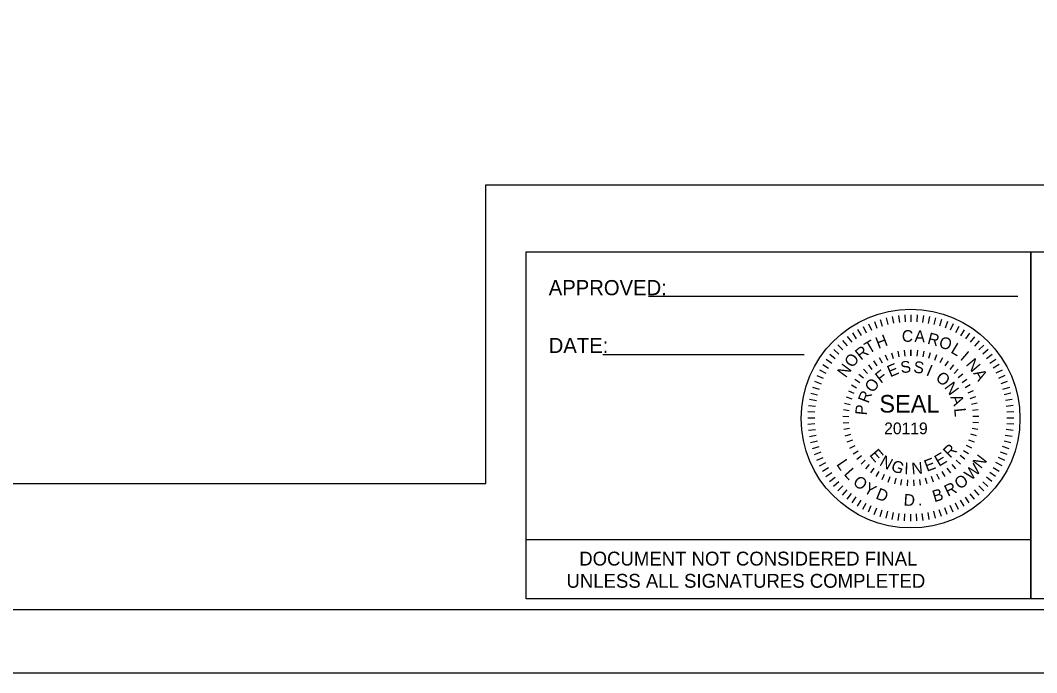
# Model space of a CAD drawing. Extents: x 1613335 to 1618399, y 897277 to 901877.
# Drawn here: x 1616057 to 1617265, y 898577 to 899353 of the extents above; entities that cross this region are included whole.
import ezdxf

# ---------------------------------------------------------------- set-up
doc = ezdxf.new("R2010")
doc.units = 0
for name, color, linetype in [('Default', 7, 'Continuous'), ('DEV BORDER CELL', 7, 'Continuous'), ('Scratch_Level_0', 7, 'Continuous'), ('Sheet Plot Border Outside CELL', 7, 'Continuous'), ('Sheet Sticker Exception Certification CELL', 7, 'Continuous')]:
    doc.layers.add(name, color=color, linetype=linetype)

msp = doc.modelspace()

# ---------------------------------------------------------------- linework, layer by layer
at = {"layer": 'Default'}
for p, q in [((1617072.2, 898994.8), (1617075.1, 898986.9)), ((1617079.2, 898997.2), (1617081.6, 898989.2)), ((1617086.3, 898999.1), (1617088.3, 898991)), ((1617093.5, 899000.7), (1617095, 898992.5)), ((1617100.9, 899001.8), (1617101.9, 898993.5)), ((1617108.2, 899002.5), (1617108.7, 898994.1)), ((1617115.7, 899002.7), (1617115.6, 898994.3)), ((1617123.1, 899002.4), (1617122.6, 898994.1)), ((1617130.4, 899001.8), (1617129.4, 898993.5)), ((1617137.8, 899000.7), (1617136.2, 898992.4)), ((1617145, 898999.1), (1617143, 898991)), ((1617152.1, 898997.1), (1617149.6, 898989.1)), ((1617159.1, 898994.7), (1617156.2, 898986.9)), ((1617046, 898981), (1617050.7, 898974.2)), ((1617052.2, 898985.1), (1617056.5, 898977.9)), ((1617058.7, 898988.7), (1617062.5, 898981.3)), ((1617065.3, 898991.9), (1617068.7, 898984.3)), ((1617166, 898991.8), (1617162.5, 898984.2)), ((1617172.6, 898988.6), (1617168.7, 898981.2)), ((1617179.1, 898984.9), (1617174.7, 898977.8)), ((1617185.3, 898980.9), (1617180.5, 898974)), ((1617034.3, 898971.9), (1617039.8, 898965.7)), ((1617040, 898976.7), (1617045.2, 898970.1)), ((1617191.3, 898976.5), (1617186.1, 898969.9)), ((1617196.9, 898971.8), (1617191.4, 898965.5)), ((1617023.8, 898961.5), (1617030.1, 898955.9)), ((1617028.9, 898966.8), (1617034.8, 898960.9)), ((1617092.5, 898957.5), (1617094.5, 898950.8)), ((1617100.1, 898959.4), (1617101.4, 898952.5)), ((1617107.8, 898960.5), (1617108.5, 898953.6)), ((1617115.6, 898960.9), (1617115.6, 898953.9)), ((1617115.6, 898953.9), (1617115.6, 898960.9)), ((1617123.4, 898960.5), (1617122.7, 898953.6)), ((1617131.1, 898959.4), (1617129.8, 898952.5)), ((1617138.7, 898957.5), (1617136.7, 898950.8)), ((1617202.3, 898966.7), (1617196.4, 898960.8)), ((1617207.4, 898961.3), (1617201.1, 898955.7)), ((1617014.7, 898949.8), (1617021.6, 898945.1)), ((1617019.1, 898955.8), (1617025.7, 898950.6)), ((1617071.3, 898947.7), (1617075.1, 898941.9)), ((1617078, 898951.7), (1617081.3, 898945.5)), ((1617085.1, 898954.9), (1617087.8, 898948.5)), ((1617146.1, 898954.9), (1617143.5, 898948.4)), ((1617153.2, 898951.6), (1617149.9, 898945.4)), ((1617159.9, 898947.6), (1617156.1, 898941.8)), ((1617212.1, 898955.6), (1617205.6, 898950.4)), ((1617216.5, 898949.6), (1617209.6, 898944.9)), ((1617007, 898937.1), (1617014.4, 898933.2)), ((1617010.7, 898943.6), (1617017.8, 898939.3)), ((1617059.1, 898937.9), (1617064, 898932.9)), ((1617065, 898943.1), (1617069.3, 898937.7)), ((1617166.2, 898943), (1617161.8, 898937.6)), ((1617172, 898937.8), (1617167.2, 898932.8)), ((1617220.5, 898943.4), (1617213.4, 898939.1)), ((1617224.2, 898936.9), (1617216.8, 898933.1)), ((1617000.9, 898923.6), (1617008.7, 898920.7)), ((1617003.8, 898930.5), (1617011.4, 898927.1)), ((1617049.1, 898926), (1617054.8, 898922.1)), ((1617053.8, 898932.2), (1617059.1, 898927.7)), ((1617177.4, 898932.1), (1617172, 898927.6)), ((1617182.1, 898925.9), (1617176.4, 898921.9)), ((1617227.4, 898930.3), (1617219.8, 898926.9)), ((1617230.2, 898923.4), (1617222.4, 898920.5)), ((1616996.5, 898909.5), (1617004.6, 898907.5)), ((1616998.5, 898916.7), (1617006.5, 898914.2)), ((1617041.5, 898912.4), (1617047.9, 898909.6)), ((1617044.9, 898919.4), (1617051, 898916)), ((1617186.2, 898919.3), (1617180.1, 898915.9)), ((1617189.7, 898912.3), (1617183.3, 898909.5)), ((1617232.7, 898916.4), (1617224.7, 898914)), ((1617234.6, 898909.3), (1617226.5, 898907.3)), ((1616994.9, 898902.3), (1617003.2, 898900.8)), ((1617036.6, 898897.6), (1617043.4, 898896.1)), ((1617038.7, 898905.1), (1617045.3, 898902.9)), ((1617192.4, 898905), (1617185.8, 898902.8)), ((1617194.5, 898897.4), (1617187.7, 898895.9)), ((1617236.2, 898902), (1617228, 898900.6)), ((1616993.1, 898887.6), (1617001.5, 898887.1)), ((1616993.8, 898894.9), (1617002.1, 898893.9)), ((1617035.3, 898889.9), (1617042.2, 898889)), ((1617195.8, 898889.7), (1617188.9, 898888.9)), ((1617237.3, 898894.7), (1617229, 898893.7)), ((1617237.9, 898887.3), (1617229.6, 898886.9)), ((1616992.9, 898880.2), (1617001.3, 898880.2)), ((1616993.1, 898872.8), (1617001.5, 898873.3)), ((1617034.7, 898882.1), (1617041.7, 898881.9)), ((1617034.9, 898874.3), (1617041.9, 898874.8)), ((1617196.1, 898874.1), (1617189.2, 898874.6)), ((1617196.3, 898881.9), (1617189.4, 898881.8)), ((1617237.9, 898872.5), (1617229.6, 898873)), ((1617238.2, 898879.9), (1617229.8, 898879.9)), ((1616993.8, 898865.4), (1617002.1, 898866.4)), ((1617035.9, 898866.5), (1617042.7, 898867.7)), ((1617037.5, 898858.9), (1617044.3, 898860.7)), ((1617193.5, 898858.7), (1617186.8, 898860.6)), ((1617188.4, 898867.8), (1617195.2, 898866.6)), ((1617237.3, 898865.2), (1617229, 898866.2)), ((1616994.9, 898858.1), (1617003.1, 898859.6)), ((1616996.4, 898850.8), (1617004.6, 898852.8)), ((1617039.9, 898851.5), (1617046.5, 898853.9)), ((1617191.1, 898851.3), (1617184.6, 898853.8)), ((1617234.6, 898850.6), (1617226.5, 898852.6)), ((1617236.1, 898857.8), (1617227.9, 898859.3)), ((1616998.4, 898843.7), (1617006.4, 898846.2)), ((1617000.8, 898836.7), (1617008.7, 898839.6)), ((1617043.1, 898844.3), (1617049.3, 898847.4)), ((1617046.8, 898837.5), (1617052.8, 898841.1)), ((1617184.2, 898837.4), (1617178.2, 898841)), ((1617188, 898844.2), (1617181.7, 898847.3)), ((1617230.2, 898836.5), (1617222.3, 898839.4)), ((1617232.6, 898843.5), (1617224.6, 898846)), ((1617003.7, 898829.8), (1617011.3, 898833.2)), ((1617006.9, 898823.2), (1617014.3, 898827)), ((1617051.3, 898831), (1617056.8, 898835.3)), ((1617056.3, 898825.1), (1617061.4, 898829.8)), ((1617061.9, 898819.6), (1617066.5, 898824.8)), ((1617169.1, 898819.5), (1617164.5, 898824.7)), ((1617174.7, 898825), (1617169.6, 898829.7)), ((1617179.7, 898830.9), (1617174.2, 898835.2)), ((1617224.1, 898823), (1617216.7, 898826.9)), ((1617227.3, 898829.6), (1617219.7, 898833.1)), ((1617010.5, 898816.7), (1617017.7, 898821)), ((1617014.6, 898810.5), (1617021.4, 898815.2)), ((1617068, 898814.7), (1617072.1, 898820.3)), ((1617074.5, 898810.4), (1617078, 898816.4)), ((1617081.4, 898806.8), (1617084.4, 898813.1)), ((1617149.5, 898806.7), (1617146.6, 898813.1)), ((1617156.5, 898810.4), (1617152.9, 898816.4)), ((1617163, 898814.6), (1617158.9, 898820.3)), ((1617216.4, 898810.3), (1617209.5, 898815.1)), ((1617220.4, 898816.5), (1617213.3, 898820.9)), ((1617018.9, 898804.5), (1617025.5, 898809.7)), ((1617023.7, 898798.8), (1617029.9, 898804.4)), ((1617088.7, 898803.8), (1617091, 898810.4)), ((1617097.8, 898808.4), (1617096.1, 898801.6)), ((1617103.8, 898800.1), (1617104.8, 898807)), ((1617111.6, 898799.3), (1617111.9, 898806.3)), ((1617119.4, 898799.3), (1617119, 898806.3)), ((1617127.1, 898800.1), (1617126.1, 898807)), ((1617134.8, 898801.6), (1617133.1, 898808.3)), ((1617142.3, 898803.8), (1617140, 898810.4)), ((1617207.2, 898798.7), (1617201, 898804.2)), ((1617212, 898804.3), (1617205.4, 898809.5)), ((1617028.8, 898793.4), (1617034.7, 898799.3)), ((1617034.1, 898788.3), (1617039.7, 898794.6)), ((1617039.8, 898783.6), (1617045, 898790.2)), ((1617191.1, 898783.5), (1617185.9, 898790)), ((1617196.8, 898788.2), (1617191.2, 898794.5)), ((1617202.2, 898793.3), (1617196.3, 898799.2)), ((1617045.8, 898779.2), (1617050.5, 898786.1)), ((1617052, 898775.2), (1617056.3, 898782.3)), ((1617058.5, 898771.5), (1617062.3, 898778.9)), ((1617065.1, 898768.3), (1617068.5, 898775.9)), ((1617165.8, 898768.2), (1617162.3, 898775.8)), ((1617172.4, 898771.4), (1617168.5, 898778.8)), ((1617178.9, 898775.1), (1617174.6, 898782.2)), ((1617185.1, 898779.1), (1617180.4, 898785.9)), ((1617072, 898765.4), (1617074.9, 898773.3)), ((1617078.9, 898763), (1617081.4, 898771)), ((1617086.1, 898761), (1617088.1, 898769.1)), ((1617093.3, 898759.5), (1617094.8, 898767.7)), ((1617100.6, 898758.3), (1617101.7, 898766.6)), ((1617108, 898757.7), (1617108.5, 898766)), ((1617115.4, 898757.4), (1617115.4, 898765.8)), ((1617122.8, 898757.6), (1617122.3, 898766)), ((1617130.2, 898758.3), (1617129.2, 898766.6)), ((1617137.5, 898759.4), (1617136, 898767.6)), ((1617144.8, 898761), (1617142.8, 898769.1)), ((1617151.9, 898762.9), (1617149.4, 898770.9)), ((1617158.9, 898765.4), (1617156, 898773.2))]:
    msp.add_line(p, q, dxfattribs=at)
at = {"layer": 'DEV BORDER CELL'}
for p, q in [((1616803.6, 899024.6), (1617242.7, 899024.6)), ((1617258.1, 899007.1), (1617258.1, 898665.1)), ((1616749.3, 898955.4), (1616988.7, 898955.4))]:
    msp.add_line(p, q, dxfattribs=at)
for points in [[(1618323.6, 901802.3), (1613823.6, 901802.3), (1613823.6, 898652.3), (1618323.6, 898652.3)], [(1616658, 899077.6), (1617258.1, 899077.6), (1617258.1, 898665.1), (1616658, 898665.1)], [(1617258.1, 899077.6), (1617600.1, 899077.6), (1617600.1, 898665.1), (1617258.1, 898665.1)]]:
    msp.add_lwpolyline(points, close=True, dxfattribs=at)
msp.add_circle((1617115.3, 898879.3), 130, dxfattribs=at)
at = {"layer": 'Scratch_Level_0'}
msp.add_lwpolyline([(1618173.6, 901652.3), (1613973.6, 901652.3), (1613973.6, 898802.3), (1616610.1, 898802.3), (1616610.1, 899157.1), (1618173.6, 899157.1)], close=True, dxfattribs=at)
at = {"layer": 'Sheet Plot Border Outside CELL'}
msp.add_lwpolyline([(1613334.6, 898577.3), (1618398.6, 898577.3), (1618398.6, 901877.3), (1613334.6, 901877.3)], close=True, dxfattribs=at)
at = {"layer": 'Sheet Sticker Exception Certification CELL'}
for p, q in [((1616658, 898665.1), (1616658, 898735.6)), ((1616658, 898735.6), (1617258.1, 898735.6)), ((1617258.1, 898735.6), (1617258.1, 898665.1)), ((1617258.1, 898665.1), (1616658, 898665.1))]:
    msp.add_line(p, q, dxfattribs=at)

# ---------------------------------------------------------------- texts
at = {"layer": 'Default'}
for s, height, rotation, p in [('C', 13.9, 357.3039, (1617104.5, 898970.8)), ('A', 13.9, 357.3039, (1617119.7, 898970.5)), ('R', 13.9, 345.2946, (1617134.4, 898968.4)), ('T', 13.9, 30.4466, (1617065.6, 898955.8)), ('H', 13.9, 21.0146, (1617076.8, 898961.9)), ('O', 13.9, 342.2378, (1617147.9, 898964.4)), ('L', 13.9, 329.1015, (1617162.1, 898958.2)), ('R', 13.9, 38.6075, (1617056.2, 898948)), ('I', 13.9, 319.5261, (1617173.3, 898950.1)), ('N', 13.9, 53.6237, (1617038.1, 898926.9)), ('O', 13.9, 51.6643, (1617046.1, 898938.7)), ('E', 13.9, 22.8914, (1617091, 898928.2)), ('S', 13.9, 7.5951, (1617104.1, 898933)), ('S', 13.9, 352.2989, (1617118, 898934.1)), ('N', 13.9, 310.2316, (1617180.3, 898943.5)), ('F', 13.9, 38.1876, (1617079.9, 898920.4)), ('I', 13.9, 337.0026, (1617132.8, 898931.1)), ('O', 13.9, 321.7064, (1617144, 898925.7)), ('A', 13.9, 300.4641, (1617189.4, 898933.2)), ('O', 13.9, 53.4838, (1617070.6, 898909.1)), ('N', 13.9, 306.4101, (1617154.7, 898916.4)), ('R', 13.9, 68.7801, (1617065.1, 898896.6)), ('SEAL', 20.9, 359.947, (1617078.1, 898886.4)), ('A', 13.9, 291.1139, (1617162.4, 898904.9)), ('P', 13.9, 84.0763, (1617063, 898882.8)), ('L', 13.9, 275.8176, (1617166.9, 898891.2)), ('20119', 13.92, 359.947, (1617083.8, 898860.7)), ('R', 13.9, 44.5119, (1617162.1, 898831.5)), ('E', 13.9, 310.0171, (1617065.6, 898835.9)), ('N', 13.9, 330.8721, (1617077.3, 898824.3)), ('E', 13.9, 30.7408, (1617148.9, 898821.8)), ('N', 13.9, 52.154, (1617198.8, 898818.9)), ('L', 13.9, 303.882, (1617026.5, 898825)), ('G', 13.9, 339.6384, (1617090.9, 898817.7)), ('I', 13.9, 357.7332, (1617107.5, 898813.3)), ('N', 13.9, 5.3628, (1617116.9, 898812.8)), ('E', 13.9, 20.7549, (1617134.6, 898815.9)), ('W', 13.9, 43.2714, (1617187.1, 898804.9)), ('L', 13.9, 311.9538, (1617035.1, 898813)), ('O', 13.9, 34.3888, (1617173.4, 898794.5)), ('O', 13.9, 320.5966, (1617045.6, 898802.1)), ('Y', 13.9, 329.2691, (1617058.3, 898792.4)), ('R', 13.9, 25.5662, (1617159.5, 898786.2)), ('D', 13.9, 338.2416, (1617072.8, 898784.5)), ('D', 13.9, 356.0369, (1617106.6, 898776)), ('B', 13.9, 16.5636, (1617143.5, 898779.8)), ('.', 13.9, 3.7793, (1617124.2, 898775.8))]:
    msp.add_text(s, height=height, rotation=rotation, dxfattribs=at).set_placement(p)
at = {"layer": 'DEV BORDER CELL'}
for s, p in [('APPROVED:  ', (1616684.9, 899025.9)), ('DATE:  ', (1616684.9, 898957.2))]:
    msp.add_text(s, height=18, dxfattribs=at).set_placement(p)
at = {"layer": 'Sheet Sticker Exception Certification CELL'}
for s, p in [('DOCUMENT NOT CONSIDERED FINAL', (1616721.2, 898704.6)), ('UNLESS ALL SIGNATURES COMPLETED', (1616706, 898678.2))]:
    msp.add_text(s, height=16.5, dxfattribs=at).set_placement(p)

doc.saveas('drawing.dxf')
